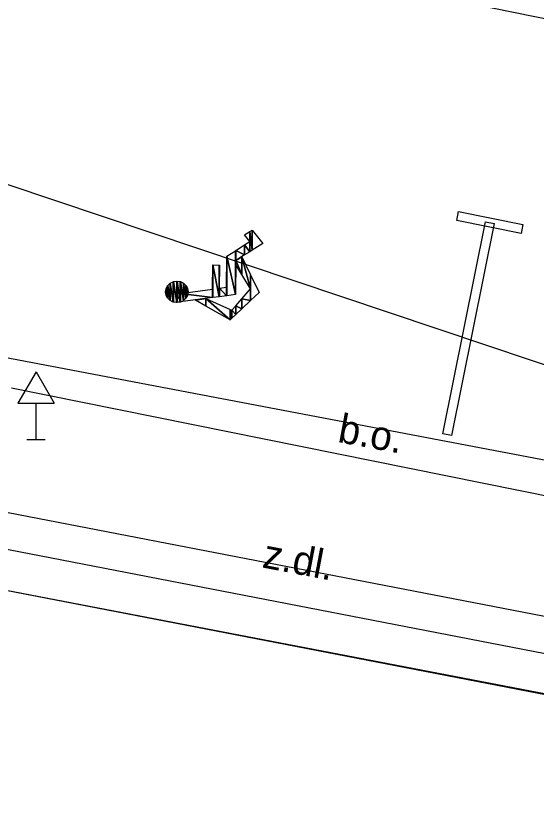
# Model space of a CAD drawing. Extents: x -601602 to -600882, y -1162594 to -1161950.
# Drawn here: x -601190.09 to -601182.89, y -1162100.58 to -1162089.58 of the extents above; entities that cross this region are included whole.
import ezdxf

# ---------------------------------------------------------------- set-up
doc = ezdxf.new("R2010")
doc.units = 0
for name, color, linetype in [('KN_Hranice parcel', 7, 'Continuous'), ('KN_Věcná břemena k části', 7, 'Continuous'), ('Vrstva 19', 7, 'Continuous'), ('Vrstva 47', 7, 'Continuous'), ('Vrstva 7', 7, 'Continuous')]:
    doc.layers.add(name, color=color, linetype=linetype)

msp = doc.modelspace()

# ---------------------------------------------------------------- linework, layer by layer
at = {"layer": 'KN_Hranice parcel'}
msp.add_line((-601214.37, -1162089.72), (-601180.06, -1162096.24), dxfattribs=at)
for points in [[(-601216.97, -1162082.96), (-601204.11, -1162087.24), (-601173.67, -1162097.46)], [(-601216.97, -1162082.96), (-601197.87, -1162086.63), (-601190.83, -1162087.99), (-601189.88, -1162088.17), (-601179.25, -1162090.33), (-601172.41, -1162091.94), (-601162.97, -1162094.53)], [(-601180.66, -1162099.38), (-601192.45, -1162097.1), (-601193.3, -1162101.65)]]:
    msp.add_lwpolyline(points, dxfattribs=at)
at = {"layer": 'KN_Věcná břemena k části'}
msp.add_lwpolyline([(-601206.94, -1162100.13), (-601206.45, -1162100.22), (-601206.1, -1162098.37), (-601205.89, -1162097.29), (-601202.51, -1162097.94), (-601200.78, -1162098.27), (-601199.06, -1162097.08), (-601198, -1162097.05), (-601190.79, -1162096.85), (-601180.55, -1162098.83), (-601177.12, -1162099.49), (-601177.23, -1162100.04), (-601176.74, -1162100.14), (-601176.53, -1162099.1), (-601180.46, -1162098.34), (-601190.75, -1162096.35), (-601198.77, -1162096.58), (-601199.22, -1162096.59), (-601200.89, -1162097.74), (-601202.41, -1162097.45), (-601206.29, -1162096.71), (-601206.59, -1162098.28)], close=True, dxfattribs=at)
at = {"layer": 'Vrstva 19'}
for p, q in [((-601189.81, -1162094.507), (-601190.06, -1162094.94)), ((-601189.81, -1162094.507), (-601189.56, -1162094.94)), ((-601190.06, -1162094.94), (-601189.56, -1162094.94)), ((-601189.81, -1162095.44), (-601189.81, -1162094.94)), ((-601189.935, -1162095.44), (-601189.685, -1162095.44))]:
    msp.add_line(p, q, dxfattribs=at)
at = {"layer": 'Vrstva 47'}
for points in [[(-601186.85, -1162092.702), (-601186.923, -1162092.61), (-601186.85, -1162092.566)], [(-601186.817, -1162092.823), (-601186.85, -1162092.566), (-601186.817, -1162092.545)], [(-601186.85, -1162092.844), (-601186.85, -1162092.566), (-601186.817, -1162092.823)], [(-601186.817, -1162092.823), (-601186.817, -1162092.545), (-601186.672, -1162092.732)], [(-601186.85, -1162092.844), (-601186.923, -1162092.749), (-601186.85, -1162092.702)], [(-601187.052, -1162093.437), (-601187.169, -1162092.904), (-601187.052, -1162092.83)], [(-601187.046, -1162092.966), (-601187.052, -1162092.83), (-601187.046, -1162092.826)], [(-601187.052, -1162093.437), (-601187.052, -1162092.83), (-601187.046, -1162092.966)], [(-601186.923, -1162092.889), (-601187.046, -1162092.826), (-601186.923, -1162092.749)], [(-601187.046, -1162092.966), (-601187.046, -1162092.826), (-601186.923, -1162092.889)], [(-601186.923, -1162092.889), (-601186.923, -1162092.749), (-601186.85, -1162092.844)], [(-601187.169, -1162093.453), (-601187.174, -1162093.334), (-601187.169, -1162092.904)], [(-601187.169, -1162093.453), (-601187.169, -1162092.904), (-601187.052, -1162093.437)], [(-601186.962, -1162093.159), (-601187.046, -1162092.966), (-601186.962, -1162092.913)], [(-601186.962, -1162093.159), (-601187.046, -1162092.966), (-601186.962, -1162092.913)], [(-601186.962, -1162093.159), (-601186.962, -1162092.913), (-601186.84, -1162093.357)], [(-601186.84, -1162093.357), (-601186.962, -1162092.913), (-601186.84, -1162093.165)], [(-601186.962, -1162093.159), (-601186.962, -1162092.913), (-601186.84, -1162093.357)], [(-601186.84, -1162093.357), (-601186.962, -1162092.913), (-601186.84, -1162093.165)], [(-601187.365, -1162093.479), (-601187.369, -1162093.36), (-601187.365, -1162093.027)], [(-601187.365, -1162093.479), (-601187.365, -1162093.027), (-601187.274, -1162093.467)], [(-601187.274, -1162093.467), (-601187.365, -1162093.027), (-601187.274, -1162093.028)], [(-601187.274, -1162093.348), (-601187.274, -1162093.028), (-601187.269, -1162093.028)], [(-601187.046, -1162093.023), (-601187.047, -1162093.021), (-601187.046, -1162092.966)], [(-601187.046, -1162093.023), (-601187.047, -1162093.021), (-601187.046, -1162092.966)], [(-601187.046, -1162093.023), (-601187.046, -1162092.966), (-601186.962, -1162093.159)], [(-601187.046, -1162093.023), (-601187.046, -1162092.966), (-601186.962, -1162093.159)], [(-601186.84, -1162093.52), (-601186.84, -1162093.165), (-601186.722, -1162093.409)], [(-601186.84, -1162093.52), (-601186.84, -1162093.165), (-601186.722, -1162093.409)], [(-601187.954, -1162093.519), (-601187.987, -1162093.31), (-601187.954, -1162093.28)], [(-601187.952, -1162093.52), (-601187.954, -1162093.28), (-601187.952, -1162093.278)], [(-601187.954, -1162093.519), (-601187.954, -1162093.28), (-601187.952, -1162093.52)], [(-601187.911, -1162093.541), (-601187.952, -1162093.278), (-601187.911, -1162093.259)], [(-601187.952, -1162093.52), (-601187.952, -1162093.278), (-601187.911, -1162093.541)], [(-601187.908, -1162093.541), (-601187.911, -1162093.259), (-601187.908, -1162093.257)], [(-601187.911, -1162093.541), (-601187.911, -1162093.259), (-601187.908, -1162093.541)], [(-601187.863, -1162093.548), (-601187.908, -1162093.257), (-601187.863, -1162093.251)], [(-601187.908, -1162093.541), (-601187.908, -1162093.257), (-601187.863, -1162093.548)], [(-601187.859, -1162093.548), (-601187.863, -1162093.251), (-601187.859, -1162093.25)], [(-601187.863, -1162093.548), (-601187.863, -1162093.251), (-601187.859, -1162093.548)], [(-601187.859, -1162093.548), (-601187.859, -1162093.25), (-601187.815, -1162093.542)], [(-601187.815, -1162093.542), (-601187.859, -1162093.25), (-601187.815, -1162093.258)], [(-601187.815, -1162093.542), (-601187.815, -1162093.258), (-601187.811, -1162093.54)], [(-601187.811, -1162093.54), (-601187.815, -1162093.258), (-601187.811, -1162093.258)], [(-601187.811, -1162093.54), (-601187.811, -1162093.258), (-601187.771, -1162093.521)], [(-601187.771, -1162093.521), (-601187.811, -1162093.258), (-601187.771, -1162093.278)], [(-601187.771, -1162093.521), (-601187.771, -1162093.278), (-601187.768, -1162093.518)], [(-601187.768, -1162093.518), (-601187.771, -1162093.278), (-601187.768, -1162093.28)], [(-601187.768, -1162093.518), (-601187.768, -1162093.28), (-601187.736, -1162093.488)], [(-601187.736, -1162093.488), (-601187.768, -1162093.28), (-601187.736, -1162093.311)], [(-601188.01, -1162093.444), (-601188.017, -1162093.398), (-601188.01, -1162093.358)], [(-601188.009, -1162093.446), (-601188.01, -1162093.358), (-601188.009, -1162093.352)], [(-601188.01, -1162093.444), (-601188.01, -1162093.358), (-601188.009, -1162093.446)], [(-601187.989, -1162093.486), (-601188.009, -1162093.352), (-601187.989, -1162093.314)], [(-601188.009, -1162093.446), (-601188.009, -1162093.352), (-601187.989, -1162093.486)], [(-601187.987, -1162093.488), (-601187.989, -1162093.314), (-601187.987, -1162093.31)], [(-601187.989, -1162093.486), (-601187.989, -1162093.314), (-601187.987, -1162093.488)], [(-601187.987, -1162093.488), (-601187.987, -1162093.31), (-601187.954, -1162093.519)], [(-601187.369, -1162093.479), (-601187.813, -1162093.42), (-601187.369, -1162093.36)], [(-601187.736, -1162093.488), (-601187.736, -1162093.311), (-601187.734, -1162093.485)], [(-601187.734, -1162093.485), (-601187.736, -1162093.311), (-601187.734, -1162093.313)], [(-601187.734, -1162093.485), (-601187.734, -1162093.313), (-601187.713, -1162093.447)], [(-601187.713, -1162093.447), (-601187.734, -1162093.313), (-601187.713, -1162093.353)], [(-601187.713, -1162093.447), (-601187.713, -1162093.353), (-601187.712, -1162093.441)], [(-601187.712, -1162093.441), (-601187.713, -1162093.353), (-601187.712, -1162093.355)], [(-601187.712, -1162093.441), (-601187.712, -1162093.355), (-601187.705, -1162093.401)], [(-601187.369, -1162093.479), (-601187.369, -1162093.36), (-601187.365, -1162093.479)], [(-601187.274, -1162093.467), (-601187.274, -1162093.348), (-601187.269, -1162093.466)], [(-601187.269, -1162093.466), (-601187.274, -1162093.348), (-601187.269, -1162093.348)], [(-601187.174, -1162093.454), (-601187.269, -1162093.348), (-601187.174, -1162093.334)], [(-601187.269, -1162093.466), (-601187.269, -1162093.348), (-601187.174, -1162093.454)], [(-601187.174, -1162093.454), (-601187.174, -1162093.334), (-601187.169, -1162093.453)], [(-601186.84, -1162093.52), (-601186.962, -1162093.496), (-601186.84, -1162093.357)], [(-601186.84, -1162093.52), (-601186.962, -1162093.496), (-601186.84, -1162093.357)], [(-601187.813, -1162093.538), (-601187.872, -1162093.546), (-601187.813, -1162093.42)], [(-601187.813, -1162093.538), (-601187.813, -1162093.42), (-601187.369, -1162093.479)], [(-601187.462, -1162093.596), (-601187.604, -1162093.516), (-601187.462, -1162093.491)], [(-601187.462, -1162093.596), (-601187.604, -1162093.516), (-601187.462, -1162093.491)], [(-601187.462, -1162093.596), (-601187.462, -1162093.491), (-601187.46, -1162093.597)], [(-601187.46, -1162093.597), (-601187.462, -1162093.491), (-601187.46, -1162093.492)], [(-601187.462, -1162093.596), (-601187.462, -1162093.491), (-601187.46, -1162093.597)], [(-601187.46, -1162093.597), (-601187.462, -1162093.491), (-601187.46, -1162093.492)], [(-601187.46, -1162093.597), (-601187.46, -1162093.492), (-601187.124, -1162093.786)], [(-601187.124, -1162093.786), (-601187.46, -1162093.492), (-601187.124, -1162093.643)], [(-601187.46, -1162093.597), (-601187.46, -1162093.492), (-601187.124, -1162093.786)], [(-601187.124, -1162093.786), (-601187.46, -1162093.492), (-601187.124, -1162093.643)], [(-601186.962, -1162093.634), (-601187.046, -1162093.592), (-601186.962, -1162093.496)], [(-601186.962, -1162093.634), (-601187.046, -1162093.592), (-601186.962, -1162093.496)], [(-601186.962, -1162093.634), (-601186.962, -1162093.496), (-601186.84, -1162093.52)], [(-601186.962, -1162093.634), (-601186.962, -1162093.496), (-601186.84, -1162093.52)], [(-601187.047, -1162093.714), (-601187.1, -1162093.653), (-601187.047, -1162093.593)], [(-601187.047, -1162093.714), (-601187.1, -1162093.653), (-601187.047, -1162093.593)], [(-601187.046, -1162093.713), (-601187.047, -1162093.593), (-601187.046, -1162093.592)], [(-601187.046, -1162093.713), (-601187.047, -1162093.593), (-601187.046, -1162093.592)], [(-601187.047, -1162093.714), (-601187.047, -1162093.593), (-601187.046, -1162093.713)], [(-601187.047, -1162093.714), (-601187.047, -1162093.593), (-601187.046, -1162093.713)], [(-601187.046, -1162093.713), (-601187.046, -1162093.592), (-601186.962, -1162093.634)], [(-601187.046, -1162093.713), (-601187.046, -1162093.592), (-601186.962, -1162093.634)], [(-601187.124, -1162093.786), (-601187.124, -1162093.643), (-601187.1, -1162093.764)], [(-601187.1, -1162093.764), (-601187.124, -1162093.643), (-601187.1, -1162093.653)], [(-601187.124, -1162093.786), (-601187.124, -1162093.643), (-601187.1, -1162093.764)], [(-601187.1, -1162093.764), (-601187.124, -1162093.643), (-601187.1, -1162093.653)], [(-601187.1, -1162093.764), (-601187.1, -1162093.653), (-601187.047, -1162093.714)], [(-601187.1, -1162093.764), (-601187.1, -1162093.653), (-601187.047, -1162093.714)]]:
    msp.add_lwpolyline(points, close=True, dxfattribs=at)
at = {"layer": 'Vrstva 7'}
for p, q in [((-601179.57, -1162096.866), (-601190.15, -1162094.73)), ((-601174.7, -1162100.51), (-601192.47, -1162097.1))]:
    msp.add_line(p, q, dxfattribs=at)
for points in [[(-601183.097, -1162092.591), (-601183.987, -1162092.412), (-601183.963, -1162092.289), (-601183.073, -1162092.468)], [(-601183.469, -1162092.452), (-601184.06, -1162095.388), (-601184.182, -1162095.364), (-601183.591, -1162092.428)]]:
    msp.add_lwpolyline(points, close=True, dxfattribs=at)
msp.add_arc((-601218.466, -1162262.792), 176.968, 77.21704, 79.72849, dxfattribs=at)

# ---------------------------------------------------------------- texts
for s, rotation, p in [('b.o.', 349.4716, (-601185.649, -1162095.474)), ('z.dl.', 349.2301, (-601186.693, -1162097.21))]:
    msp.add_text(s, height=0.4, rotation=rotation, dxfattribs=at).set_placement(p)

doc.saveas('drawing.dxf')
